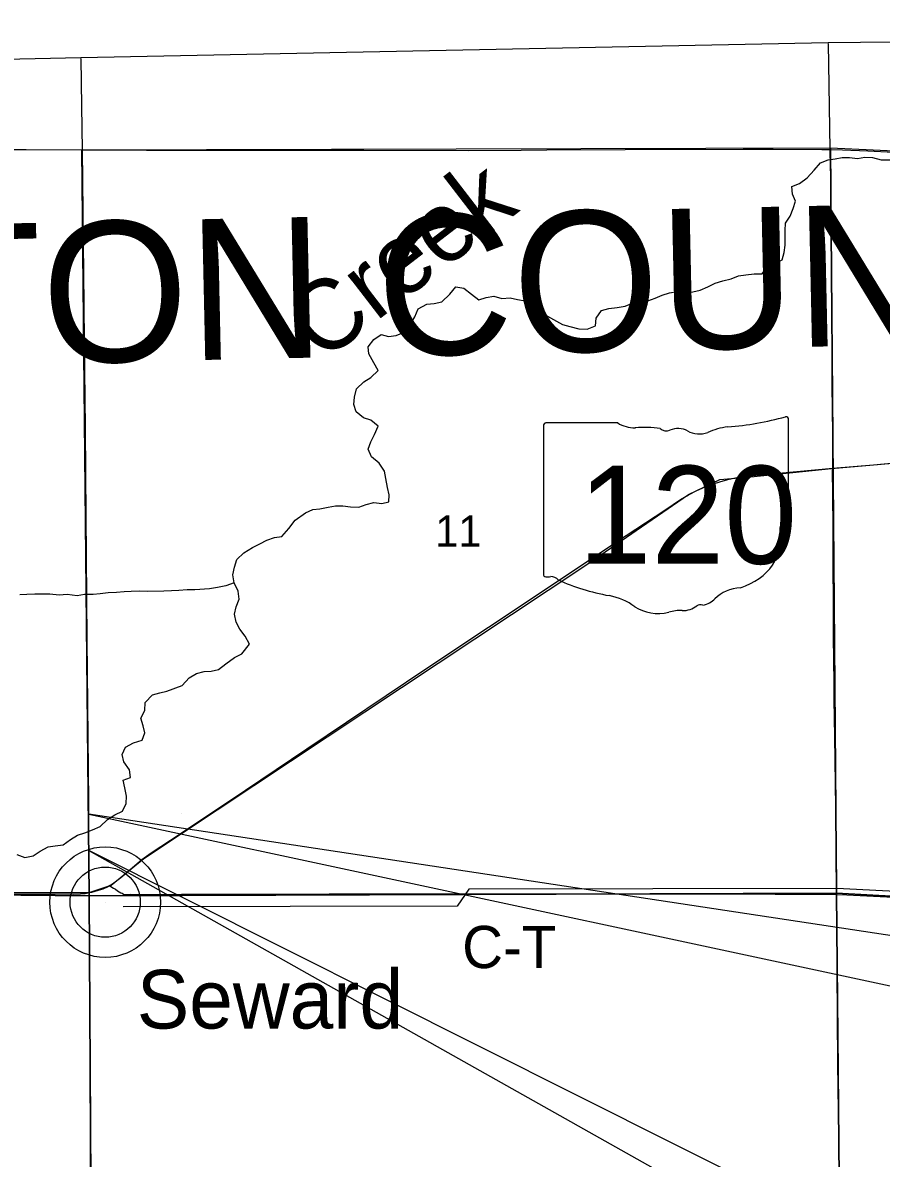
# Model space of a CAD drawing. Extents: x 0 to 34, y 0 to 22.
# Drawn here: x 5.396 to 6.55, y 19.3 to 20.828 of the extents above; entities that cross this region are included whole.
import ezdxf

# ---------------------------------------------------------------- set-up
doc = ezdxf.new("R2010")
doc.units = 0
for name, color, linetype in [('Default', 7, 'Continuous'), ('GM_X_County_Road', 7, 'Continuous'), ('GM_X_County_Road_Text', 7, 'Continuous'), ('GM_X_County_Text', 7, 'Continuous'), ('GM_X_Minor_River', 7, 'Continuous'), ('GM_X_Minor_River_Text', 7, 'Continuous'), ('GM_X_Rail_Line', 7, 'Continuous'), ('GM_X_Section', 7, 'Continuous'), ('GM_X_Section_Text', 7, 'Continuous'), ('GM_X_State_Location', 7, 'Continuous'), ('GM_X_State_Route', 7, 'Continuous'), ('GM_X_State_Shield', 7, 'Continuous'), ('GM_X_Township_Road', 7, 'Continuous'), ('GM_X_Unincorporated', 7, 'Continuous'), ('GM_X_Unincorporated_Location', 7, 'Continuous'), ('GM_X_Unincorporated_Text', 7, 'Continuous'), ('SH_Cut_Line', 7, 'Continuous'), ('SH_Text', 7, 'Continuous')]:
    doc.layers.add(name, color=color, linetype=linetype)

msp = doc.modelspace()

# ---------------------------------------------------------------- linework, layer by layer
at = {"layer": 'Default'}
msp.add_lwpolyline([(7.476, 20.811), (6.4789, 20.8005), (5.4741, 20.7803), (4.4698, 20.7584)], dxfattribs=at)
at = {"layer": 'GM_X_County_Road'}
for points in [[(5.5117, 19.6664), (5.5143, 19.6654), (5.5179, 19.6635), (5.5204, 19.6618), (5.5234, 19.6596), (5.5255, 19.6583), (5.5278, 19.657), (5.5293, 19.6564), (5.5315, 19.6554), (5.5335, 19.655), (5.5362, 19.655), (5.5407, 19.6551), (5.5532, 19.6549), (5.6092, 19.6554), (5.6496, 19.6554), (5.7676, 19.6554), (5.808, 19.6555), (5.9447, 19.6557), (6.0038, 19.6557), (6.1622, 19.6555), (6.4077, 19.6553), (6.4791, 19.6551), (6.4906, 19.6548)], [(6.4906, 19.6548), (6.5039, 19.6545), (6.7366, 19.6428), (6.8359, 19.6379), (6.8701, 19.6362), (6.9787, 19.6306), (7.0469, 19.6267), (7.0872, 19.6241), (7.1927, 19.6183), (7.2516, 19.6148), (7.2826, 19.613), (7.3353, 19.6099), (7.4563, 19.603), (7.4829, 19.602)]]:
    msp.add_lwpolyline(points, dxfattribs=at)
at = {"layer": 'GM_X_Minor_River'}
for points in [[(6.1217, 20.4219), (6.1315, 20.4191), (6.1436, 20.416), (6.1546, 20.4155), (6.166, 20.4199), (6.1669, 20.4302), (6.1738, 20.4407), (6.1837, 20.4433), (6.1951, 20.4447), (6.2057, 20.4465), (6.2156, 20.4505), (6.2255, 20.4512), (6.2361, 20.4534), (6.246, 20.4571), (6.2556, 20.4612), (6.2655, 20.4641), (6.2757, 20.4659), (6.2875, 20.4654), (6.2969, 20.4657), (6.3068, 20.4679), (6.3171, 20.4723), (6.327, 20.4775), (6.3373, 20.4805), (6.3483, 20.483), (6.3582, 20.4871), (6.3681, 20.4885), (6.3791, 20.4899), (6.3901, 20.4898), (6.3974, 20.4996), (6.4069, 20.5033), (6.4168, 20.5089), (6.4196, 20.5187), (6.4212, 20.5286), (6.421, 20.5388), (6.4211, 20.5483), (6.4216, 20.5578), (6.4277, 20.5676), (6.4317, 20.5778), (6.4348, 20.5876), (6.4307, 20.5971), (6.4301, 20.6074), (6.4404, 20.6115), (6.4507, 20.619), (6.4599, 20.6291), (6.4687, 20.6393), (6.4786, 20.6433), (6.4881, 20.6444), (6.4976, 20.6462), (6.5075, 20.6465), (6.5181, 20.6452), (6.5283, 20.6466), (6.5386, 20.6465), (6.5499, 20.6434), (6.5708, 20.6432)], [(5.5296, 19.843), (5.5342, 19.8532), (5.5449, 19.8588), (5.5563, 19.8624), (5.5602, 19.8723), (5.5577, 19.8818), (5.5544, 19.8921), (5.5602, 19.9022), (5.5603, 19.9133), (5.5702, 19.9234), (5.5801, 19.926), (5.5896, 19.9285), (5.6102, 19.9359), (5.6198, 19.9461), (5.6293, 19.952), (5.6396, 19.955), (5.6491, 19.9553), (5.6589, 19.9574), (5.6689, 19.9653), (5.6807, 19.9735), (5.6906, 19.9784), (5.7006, 19.9916), (5.6947, 20.0022), (5.6876, 20.0118), (5.6828, 20.0213), (5.6806, 20.032), (5.6826, 20.0418), (5.6869, 20.052), (5.6855, 20.0627), (5.6803, 20.0741), (5.6782, 20.0851), (5.6806, 20.095), (5.6837, 20.1056), (5.6933, 20.1146), (5.7047, 20.1217), (5.7146, 20.1265), (5.7242, 20.1314), (5.7345, 20.135), (5.7443, 20.1365), (5.7535, 20.1474), (5.762, 20.1583), (5.7761, 20.1684), (5.7857, 20.1729), (5.7952, 20.1735), (5.8066, 20.1761), (5.8164, 20.1775), (5.8263, 20.1778), (5.8365, 20.1762), (5.8479, 20.176), (5.8574, 20.1794), (5.8677, 20.1823), (5.8786, 20.1807), (5.8881, 20.1829), (5.8886, 20.1927), (5.8861, 20.2026), (5.8839, 20.2144), (5.8822, 20.2243), (5.8751, 20.235), (5.8649, 20.2438), (5.8605, 20.2541), (5.864, 20.2639), (5.8687, 20.2737), (5.8737, 20.2847), (5.864, 20.2928), (5.8538, 20.2959), (5.844, 20.304), (5.8411, 20.3142), (5.842, 20.3237), (5.8444, 20.3351), (5.8543, 20.3445), (5.8639, 20.3504), (5.8738, 20.3598), (5.8679, 20.3701), (5.8612, 20.382), (5.8601, 20.3915), (5.8678, 20.4013), (5.8778, 20.408), (5.8876, 20.4056), (5.8979, 20.407), (5.9078, 20.4107), (5.9166, 20.4216), (5.9232, 20.4322), (5.9274, 20.4428), (5.9393, 20.4491), (5.9491, 20.4498), (5.9594, 20.452), (5.9701, 20.4625), (5.9782, 20.4723), (5.9888, 20.4706), (5.9993, 20.4626), (6.0091, 20.4549), (6.019, 20.4578), (6.0292, 20.46), (6.0402, 20.4568), (6.0512, 20.4575), (6.061, 20.4551), (6.0712, 20.4535), (6.0826, 20.4511), (6.0912, 20.4408), (6.1013, 20.4327), (6.1217, 20.4219)], [(5.6803, 20.0741), (5.6689, 20.07), (5.6575, 20.0679), (5.6469, 20.0661), (5.6272, 20.0648), (5.6169, 20.0649), (5.6059, 20.0638), (5.5957, 20.0632), (5.5854, 20.0629), (5.5642, 20.0624), (5.5532, 20.0628), (5.5415, 20.0626), (5.532, 20.0619), (5.5221, 20.0609), (5.5107, 20.0606), (5.5001, 20.0592), (5.4906, 20.0585), (5.4789, 20.0586), (5.469, 20.0565), (5.4554, 20.0585), (5.4447, 20.0575), (5.4322, 20.0587), (5.4122, 20.0589), (5.4015, 20.0586), (5.392, 20.058)], [(5.3878, 19.7085), (5.3988, 19.7046), (5.4098, 19.7068), (5.4193, 19.7131), (5.43, 19.7191), (5.4395, 19.7201), (5.4501, 19.7216), (5.4601, 19.7287), (5.4696, 19.7346), (5.4795, 19.738), (5.4898, 19.742), (5.5001, 19.7465), (5.51, 19.7555), (5.5196, 19.7619), (5.5299, 19.7671), (5.5349, 19.7773), (5.5354, 19.7871), (5.5332, 19.7985), (5.5307, 19.8088), (5.5406, 19.8121), (5.5392, 19.8224), (5.5317, 19.8331), (5.5296, 19.843)], [(6.9733, 19.6383), (6.4904, 19.6627), (5.9957, 19.6619)], [(5.9957, 19.6619), (5.9799, 19.6389), (5.5307, 19.6384)]]:
    msp.add_lwpolyline(points, dxfattribs=at)
at = {"layer": 'GM_X_Rail_Line'}
msp.add_lwpolyline([(2.1, 19.6449), (2.4687, 19.6463), (3.2362, 19.6474), (3.7244, 19.6491), (5.0197, 19.6574), (5.4852, 19.6574), (5.5146, 19.6675), (5.5588, 19.7034), (6.1514, 20.0969), (6.291, 20.193), (6.3333, 20.2132), (6.3747, 20.2169), (6.4833, 20.2279), (7.4795, 20.3149), (8.1518, 20.3773), (8.7379, 20.4271), (8.9, 20.4441)], dxfattribs=at)
at = {"layer": 'GM_X_Section'}
for points in [[(4.4712, 20.6576), (5.4752, 20.6568), (5.485, 19.653), (4.4763, 19.663)], [(5.4752, 20.6568), (6.4819, 20.6594), (6.4898, 19.6568), (5.485, 19.653)], [(6.4819, 20.6594), (7.4085, 20.616), (7.4769, 20.6134), (7.4843, 19.6166), (7.4844, 19.6018), (6.4898, 19.6568)], [(4.4763, 19.663), (5.485, 19.653), (5.4908, 18.6512), (4.4846, 18.6535)], [(5.485, 19.653), (6.4898, 19.6568), (6.4992, 18.6508), (5.4908, 18.6512)], [(6.4898, 19.6568), (7.4844, 19.6018), (7.4927, 18.6151), (7.4929, 18.6076), (6.4992, 18.6508)]]:
    msp.add_lwpolyline(points, close=True, dxfattribs=at)
at = {"layer": 'GM_X_State_Route'}
for points in [[(5.4874, 19.1734), (5.4864, 19.4408), (5.4864, 19.4906), (5.4857, 19.6087), (5.4854, 19.6553), (5.4853, 19.6574), (5.4847, 19.6989), (5.4846, 19.7797), (5.4824, 19.9973), (5.4807, 20.2211), (5.48, 20.2833), (5.4788, 20.3983), (5.4783, 20.4481), (5.4761, 20.6568), (5.4754, 20.7154), (5.4744, 20.7797)], [(5.4853, 19.6574), (5.4888, 19.6581), (5.4979, 19.6605), (5.5038, 19.6626), (5.5096, 19.6652), (5.5117, 19.6664), (5.515, 19.6683), (5.5202, 19.6719), (5.53, 19.6797), (5.5464, 19.6939), (5.556, 19.7017), (5.5686, 19.7107), (5.6076, 19.7363), (5.6954, 19.7952), (5.778, 19.8507), (5.938, 19.9584), (6.1063, 20.0704), (6.1942, 20.1291), (6.259, 20.1721), (6.2803, 20.1862), (6.2908, 20.1926), (6.302, 20.1983), (6.3134, 20.2035), (6.3209, 20.2063), (6.3273, 20.2084), (6.3378, 20.2115), (6.3459, 20.2137), (6.3582, 20.2163), (6.3701, 20.2179), (6.3881, 20.2195), (6.4849, 20.2282), (6.5398, 20.2331), (6.6358, 20.2418)], [(4.2951, 19.6535), (4.3041, 19.6537), (4.3943, 19.6544), (4.4739, 19.6545), (4.4751, 19.6545), (4.4844, 19.6546), (4.587, 19.6552), (4.7238, 19.6564), (4.7549, 19.6563), (4.8109, 19.6561), (4.8918, 19.6564), (4.9322, 19.6565), (4.9788, 19.6565), (5.0503, 19.6563), (5.1499, 19.6563), (5.268, 19.6558), (5.3147, 19.6556), (5.3644, 19.6555), (5.4639, 19.6552), (5.4733, 19.6556), (5.4796, 19.6563), (5.4853, 19.6574)]]:
    msp.add_lwpolyline(points, dxfattribs=at)
at = {"layer": 'GM_X_State_Shield'}
for p, q in [((6.1958, 20.2892), (6.0992, 20.2892)), ((6.4256, 20.1894), (6.4256, 20.2941)), ((6.096, 20.2857), (6.096, 20.0856)), ((6.4256, 20.1894), (6.4256, 20.1894))]:
    msp.add_line(p, q, dxfattribs=at)
for centre, major_axis, start_param, end_param in [((6.0998, 20.2861), (0.00382, 0), 1.712693, 3.28349), ((6.2188, 20.3124), (0.037, 0), 4.042523, 4.731795), ((6.3082, 20.562), (0.3495, 0), 4.814394, 5.042369), ((6.4219, 20.2945), (0.00367, 0), 6.141152, 7.989035), ((6.231, 20.1768), (0.133, 0), 1.404758, 1.657858), ((6.2612, 20.2872), (0.0107, 0), 3.836095, 5.185415), ((6.2769, 20.264), (0.0222, 0), 0.950623, 2.079405), ((6.3056, 20.2958), (0.0267, 0), 4.081561, 5.145723), ((6.3528, 20.228), (0.0703, 0), 1.699011, 2.107814), ((6.4247, 20.1817), (0.00568, 0), 1.883978, 3.671073), ((6.4217, 20.189), (0.00393, 0), 5.05454, 6.418171), ((6.3886, 20.1685), (0.0341, 0), 5.934695, 6.695948), ((6.4387, 20.1456), (0.0248, 0), 2.387724, 3.262537), ((6.3278, 20.1323), (0.0874, 0), 5.101752, 6.440018), ((6.0998, 20.0851), (0.00385, 0), 3.00124, 4.508301), ((6.1004, 20.1056), (0.0294, 0), 4.665946, 4.897461), ((6.1064, 20.074), (0.0106, 0), 0.519207, 1.627899), ((6.2402, 20.2538), (0.2524, 0), 4.195997, 4.488961), ((6.3646, 20.0294), (0.0479, 0), 1.647645, 2.488434), ((6.165, 19.9957), (0.079, 0), 0.823519, 1.323587), ((6.3072, 20.0387), (0.00752, 0), 1.147584, 2.315152), ((6.304, 20.0662), (0.0282, 0), 4.937069, 5.64225), ((6.2504, 20.073), (0.0501, 0), 4.026481, 4.996735), ((6.2794, 20.0039), (0.0412, 0), 1.495662, 1.94098), ((6.283, 20.0581), (0.0267, 0), 4.691044, 5.507374)]:
    msp.add_ellipse(centre, major_axis=major_axis, ratio=0.8, start_param=start_param, end_param=end_param, dxfattribs=at)
at = {"layer": 'GM_X_Township_Road'}
for points in [[(6.4817, 20.6572), (6.48, 20.7438), (6.4791, 20.7999)], [(4.4698, 20.657), (4.4951, 20.6572), (4.5604, 20.6574), (4.828, 20.6583), (4.8715, 20.6584), (4.9617, 20.6586), (5.0364, 20.6589), (5.1111, 20.6587), (5.2168, 20.658), (5.4003, 20.6572), (5.4761, 20.6568)], [(5.4761, 20.6568), (5.4847, 20.6568), (5.5624, 20.6563), (5.6215, 20.656), (5.6868, 20.6562), (5.7209, 20.6561), (5.8546, 20.6561), (5.9946, 20.6557), (6.0661, 20.6564), (6.1003, 20.6567), (6.206, 20.6573), (6.3645, 20.6577), (6.405, 20.6577), (6.4702, 20.6572), (6.4817, 20.6572)], [(6.4849, 20.2282), (6.4852, 20.2405), (6.4849, 20.2746), (6.4843, 20.3399), (6.484, 20.4269), (6.4827, 20.5481), (6.4823, 20.5698), (6.4822, 20.6195), (6.4817, 20.6537), (6.4817, 20.6572)], [(6.4817, 20.6572), (6.498, 20.6566), (6.5323, 20.6552), (6.5665, 20.6536), (6.5905, 20.6522), (6.6483, 20.6492), (6.7683, 20.6417), (6.8335, 20.6387), (6.9268, 20.635), (6.964, 20.6333), (7.0292, 20.6294), (7.1875, 20.6196), (7.2434, 20.6168), (7.318, 20.6142), (7.4267, 20.6111), (7.4774, 20.6094)], [(6.4863, 19.974), (6.486, 19.998), (6.4855, 20.1472), (6.4852, 20.1938), (6.4848, 20.2249), (6.4849, 20.2282)], [(6.4906, 19.6548), (6.4906, 19.6718), (6.4896, 19.7401), (6.4877, 19.8675), (6.4869, 19.9173), (6.4867, 19.9359), (6.4863, 19.974)], [(6.4986, 18.6541), (6.497, 18.743), (6.4962, 18.8052), (6.4957, 18.8798), (6.4957, 18.8975), (6.4953, 18.9862), (6.495, 19.1012), (6.4948, 19.1323), (6.4942, 19.2131), (6.4931, 19.3311), (6.4919, 19.4276), (6.4911, 19.5536), (6.4905, 19.6282), (6.4906, 19.6548)]]:
    msp.add_lwpolyline(points, dxfattribs=at)
at = {"layer": 'GM_X_Unincorporated'}
for radius in [0.0744, 0.0472]:
    msp.add_circle((5.5067, 19.6445), radius, dxfattribs=at)
at = {"layer": 'GM_X_Unincorporated_Location'}
msp.add_line((5.5067, 19.6445), (5.5067, 19.6445), dxfattribs=at)
at = {"layer": 'SH_Cut_Line'}
msp.add_lwpolyline([(2.1, 20.6957), (2.1, 14.1), (8.9, 14.1), (8.9, 20.8277), (8.6079, 20.8216), (7.476, 20.811), (6.4789, 20.8005), (5.4741, 20.7803), (4.4698, 20.7584), (3.7151, 20.7343), (2.4566, 20.7022)], close=True, dxfattribs=at)
at = {"layer": 'SH_Text'}
for points in [[(5.4846, 19.763), (9.956, 18.8047), (9.956, 19.0851)], [(5.4846, 19.7138), (9.956, 17.197), (9.956, 17.4693)]]:
    msp.add_lwpolyline(points, close=True, dxfattribs=at)

# ---------------------------------------------------------------- texts
at = {"layer": 'GM_X_County_Road_Text'}
msp.add_text('C-T', height=0.05682, rotation=0, dxfattribs=at).set_placement((5.9867, 19.5558))
at = {"layer": 'GM_X_County_Text'}
msp.add_text('FULTON COUNTY', height=0.189394, rotation=1.2494, dxfattribs=at).set_placement((4.7905, 20.3554))
at = {"layer": 'GM_X_Minor_River_Text'}
msp.add_text('Creek', height=0.09477, rotation=37.5847, dxfattribs=at).set_placement((5.7976, 20.3689))
at = {"layer": 'GM_X_Section_Text'}
msp.add_text('11', height=0.04186, rotation=0, dxfattribs=at).set_placement((5.9504, 20.1229))
at = {"layer": 'GM_X_State_Location'}
for s in ['s', 'r']:
    msp.add_text(s, height=0.000189, dxfattribs=at).set_placement((5.676, 19.7769))
msp.add_text('120', height=0.000189, rotation=0, dxfattribs=at).set_placement((5.6092, 19.7632))
at = {"layer": 'GM_X_State_Shield'}
msp.add_text('120', height=0.13184, dxfattribs=at).set_placement((6.143, 20.0997))
at = {"layer": 'GM_X_Unincorporated_Text'}
msp.add_text('Seward', height=0.07898, rotation=0, dxfattribs=at).set_placement((5.5492, 19.4745))

doc.saveas('drawing.dxf')
